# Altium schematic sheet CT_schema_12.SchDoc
size 389 x 385 mm
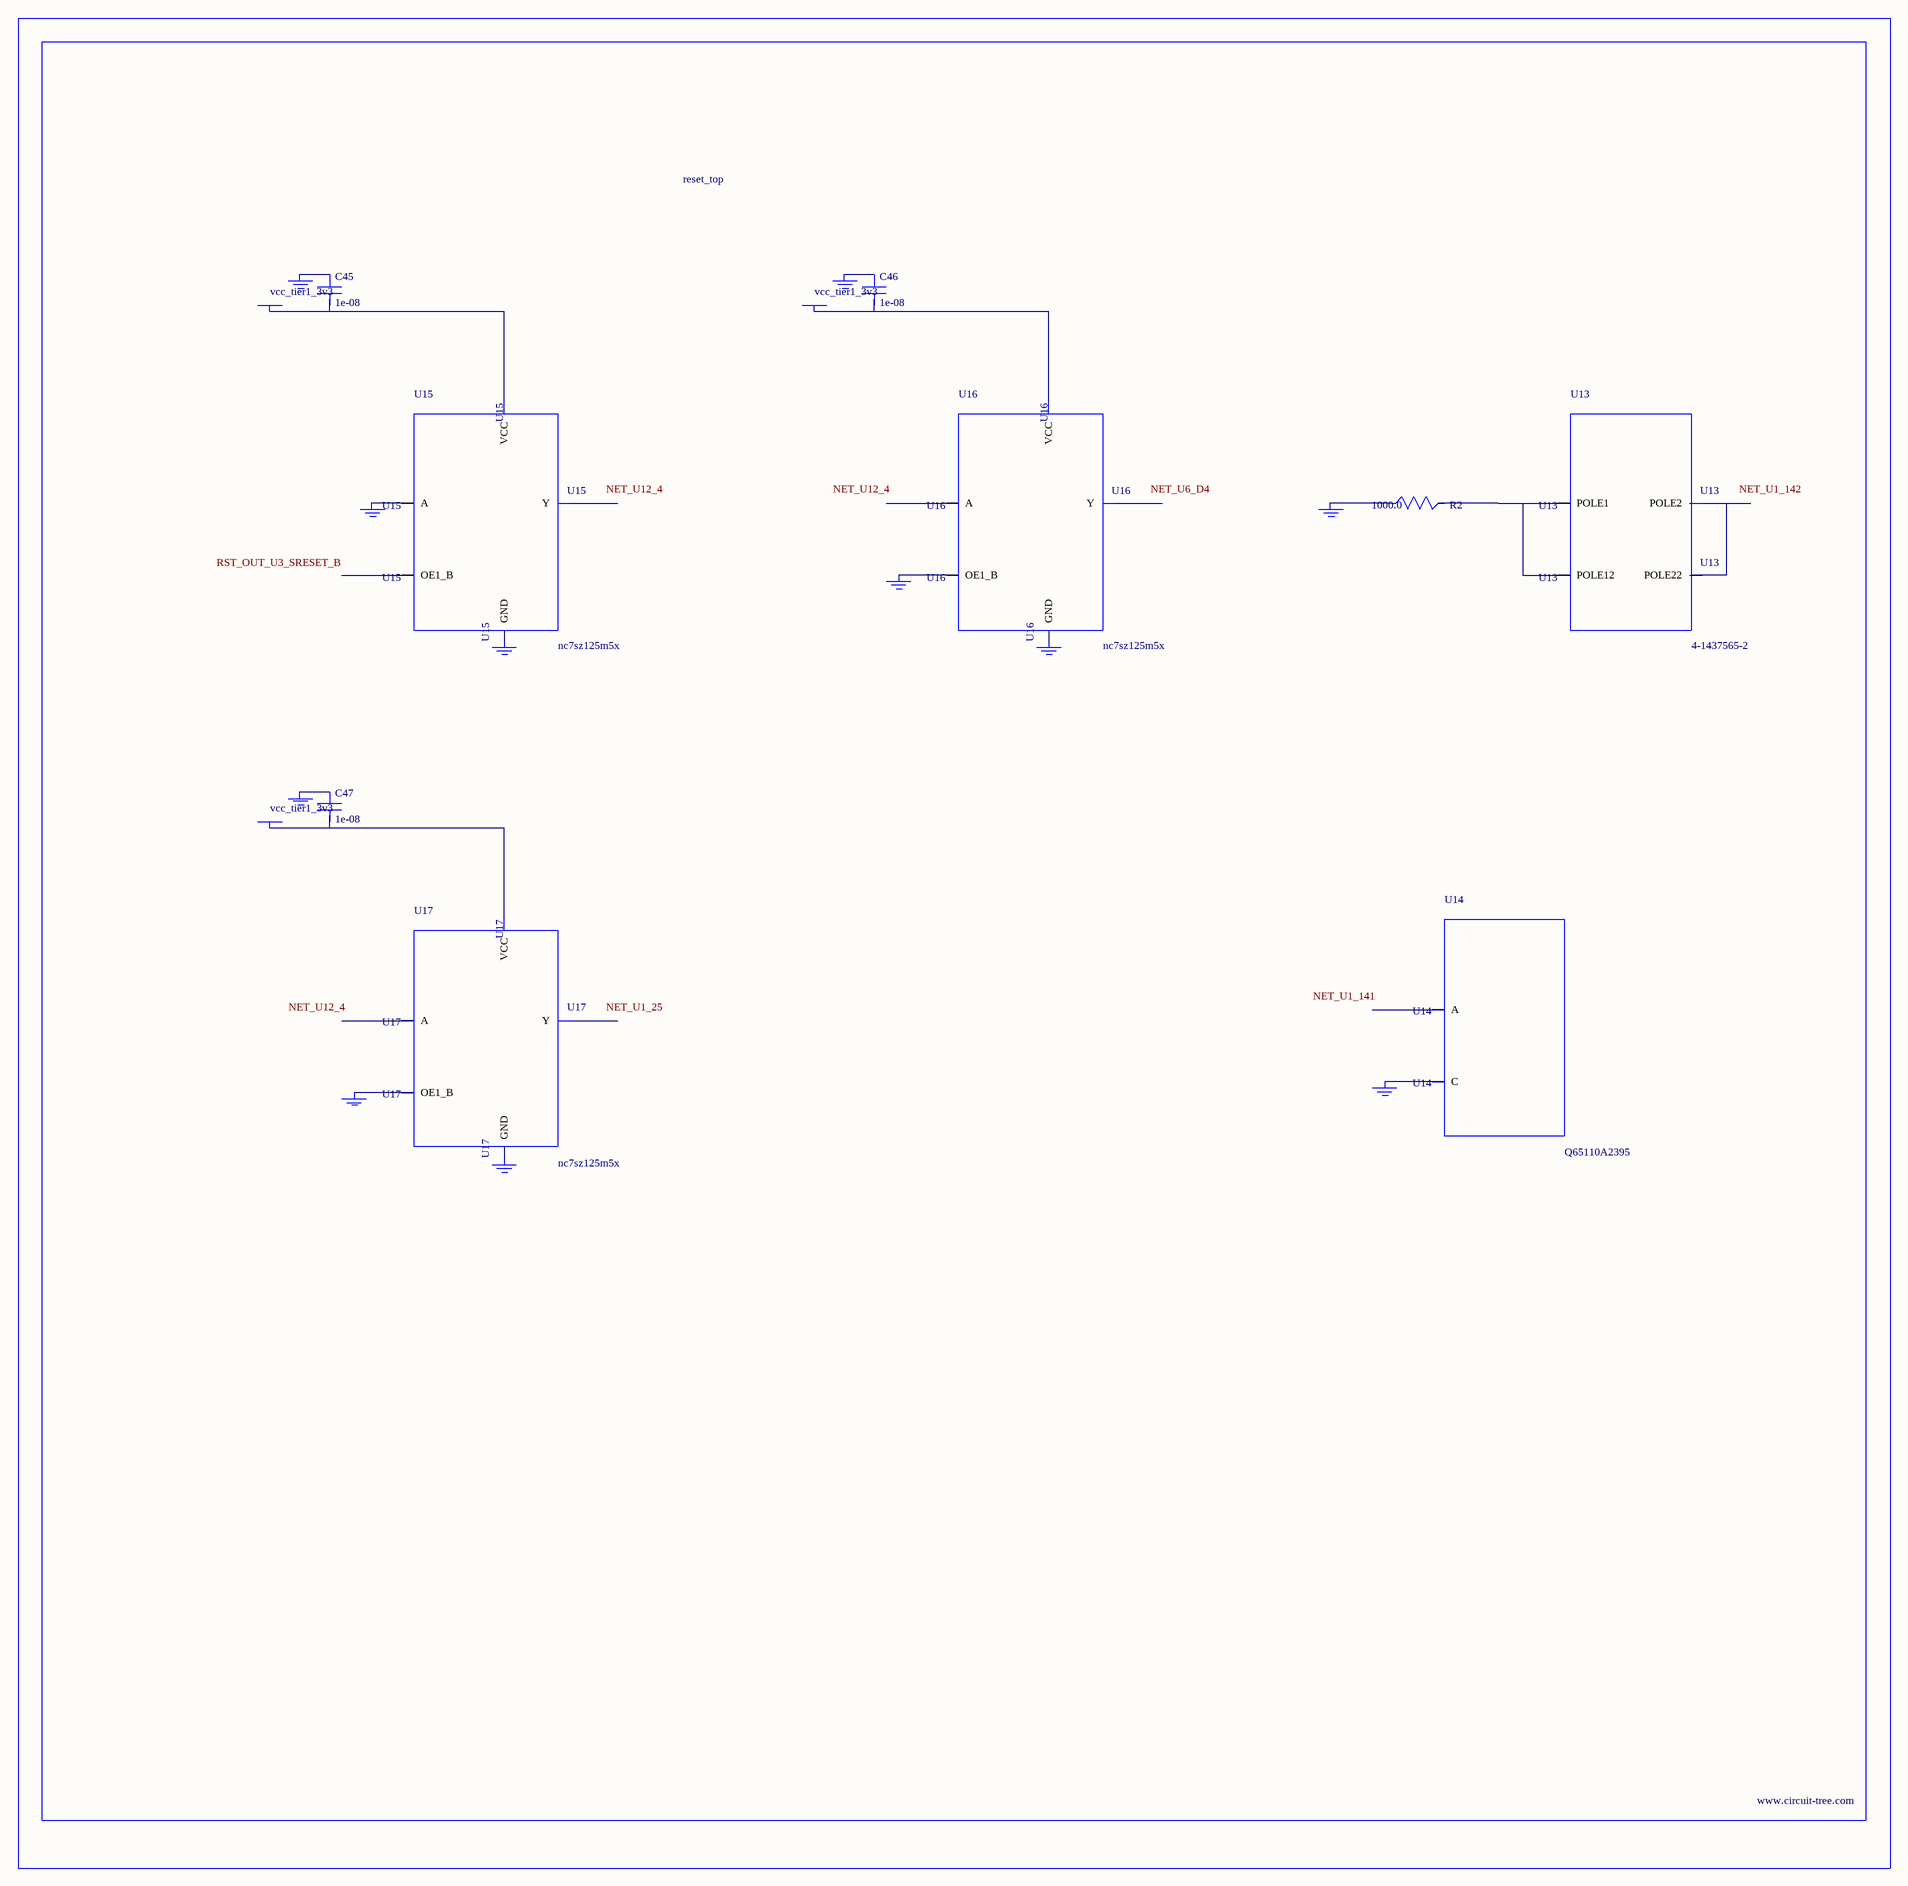
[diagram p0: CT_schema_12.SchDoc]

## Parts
BORDER11  (no value)
C45  1e-08  [C0402]
C46  1e-08  [C0402]
C47  1e-08  [C0402]
GND_INSTANCE_11_0  (no value)
GND_INSTANCE_11_1  (no value)
GND_INSTANCE_11_2  (no value)
GND_INSTANCE_11_3  (no value)
GND_INSTANCE_11_4  (no value)
GND_INSTANCE_11_5  (no value)
GND_INSTANCE_11_6  (no value)
GND_INSTANCE_11_7  (no value)
GND_INSTANCE_11_8  (no value)
GND_INSTANCE_11_9  (no value)
GND_INSTANCE_11_10  (no value)
POWER_INSTANCE_11_0  vcc_tier1_3v3
POWER_INSTANCE_11_1  vcc_tier1_3v3
POWER_INSTANCE_11_2  vcc_tier1_3v3
R2  1000.0  [R0603]
U13  4-1437565-2  [SW_4-1437565-2]
U14  Q65110A2395  [LGM67K-G1J2-24-Z]
U15  nc7sz125m5x  [NC7SZ125M5X]
U16  nc7sz125m5x  [NC7SZ125M5X]
U17  nc7sz125m5x  [NC7SZ125M5X]

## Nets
NetC45_1: C45.1 GND_INSTANCE_11_2.0(GND)
NetC45_2: C45.2 POWER_INSTANCE_11_0.0(PWR) U15.5(VCC)
NetC46_1: C46.1 GND_INSTANCE_11_5.0(GND)
NetC46_2: C46.2 POWER_INSTANCE_11_1.0(PWR) U16.5(VCC)
NetC47_1: C47.1 GND_INSTANCE_11_8.0(GND)
NetC47_2: C47.2 POWER_INSTANCE_11_2.0(PWR) U17.5(VCC)
NetGND_INSTANCE_11_0_0: GND_INSTANCE_11_0.0(GND) R2.1
NetGND_INSTANCE_11_1_0: GND_INSTANCE_11_1.0(GND) U14.C
NetGND_INSTANCE_11_3_0: GND_INSTANCE_11_3.0(GND) U15.2(A)
NetGND_INSTANCE_11_4_0: GND_INSTANCE_11_4.0(GND) U15.3(GND)
NetGND_INSTANCE_11_6_0: GND_INSTANCE_11_6.0(GND) U16.1(OE1_B)
NetGND_INSTANCE_11_7_0: GND_INSTANCE_11_7.0(GND) U16.3(GND)
NetGND_INSTANCE_11_9_0: GND_INSTANCE_11_9.0(GND) U17.1(OE1_B)
NetGND_INSTANCE_11_10_0: GND_INSTANCE_11_10.0(GND) U17.3(GND)
NetR2_2: R2.2 U13.1(POLE1) U13.2(POLE12)
NetU13_3: U13.3(POLE2) U13.4(POLE22)

Not connected (* = marked no-connect by the designer): U14 A; U15 1(OE1_B) 4(Y); U16 2(A) 4(Y); U17 2(A) 4(Y)

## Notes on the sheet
- Labels drawn without touching a wire or pin: NET_U1_25, NET_U1_141, NET_U1_142, NET_U6_D4, NET_U12_4, RST_OUT_U3_SRESET_B

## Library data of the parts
BORDER11 = BORDER_PAGE11
C45-C47 = C0402C103K3RAC
GND_INSTANCE_11_0-GND_INSTANCE_11_10 = GND
POWER_INSTANCE_11_0-POWER_INSTANCE_11_2 = PWR
R2 = RC0603JR-071KL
